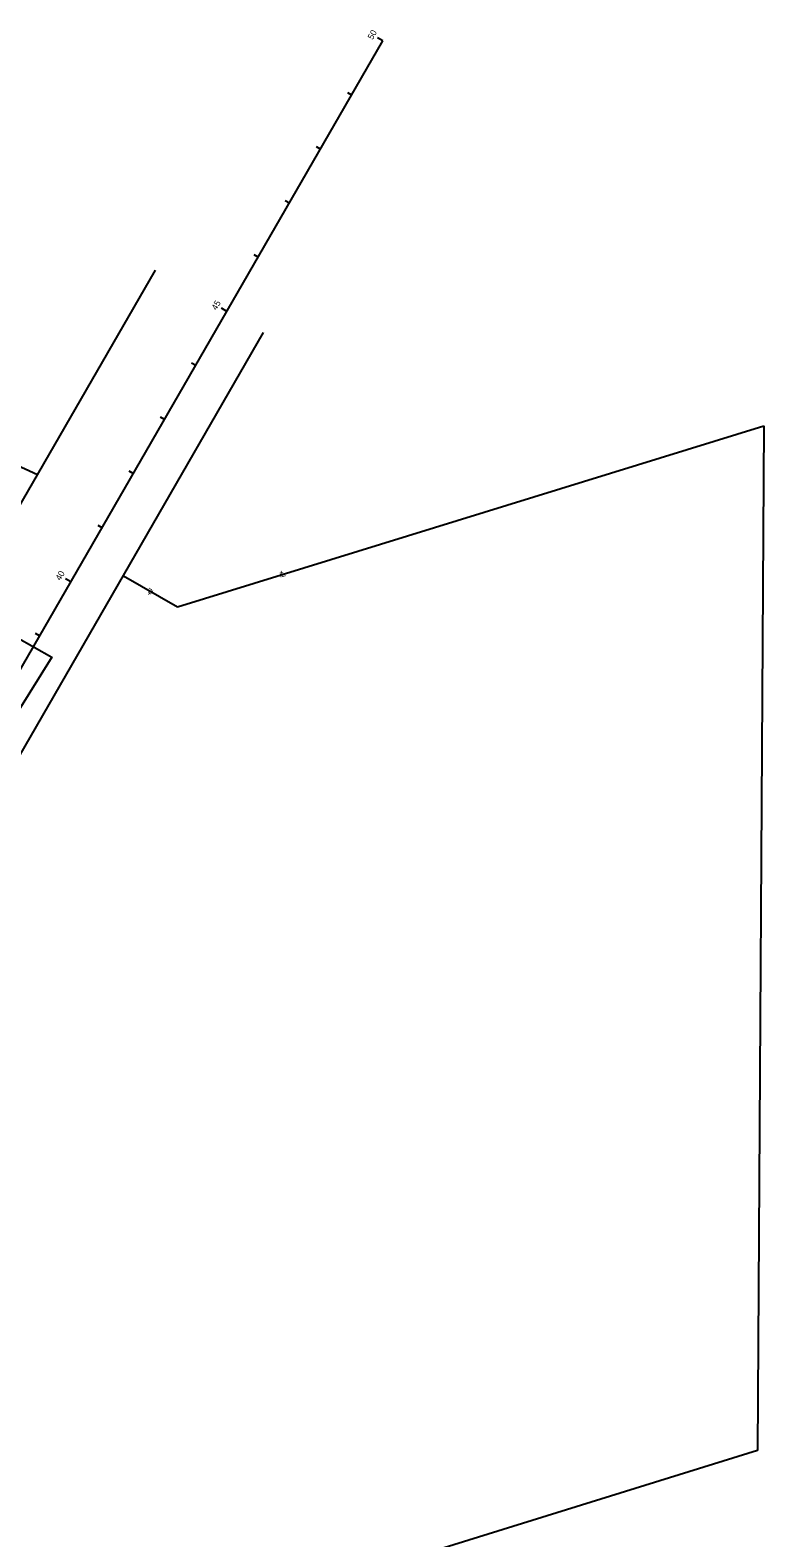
# Model space of a CAD drawing. Extents: x 2003883 to 2008298, y 399149 to 424047.
# Drawn here: x 2007122 to 2008298, y 401725 to 404139 of the extents above; entities that cross this region are included whole.
import ezdxf

# ---------------------------------------------------------------- set-up
doc = ezdxf.new("R2010")
doc.units = 0
for name, color, linetype in [('BaselineSurvey', 7, 'Continuous'), ('BaselineTextWt2', 7, 'Continuous'), ('ConstLimits', 7, 'Continuous'), ('PropertyLine_ep', 7, 'Continuous'), ('PropertyLineSymbol_ep', 7, 'Continuous'), ('RWLine_ep', 7, 'Continuous')]:
    doc.layers.add(name, color=color, linetype=linetype)

msp = doc.modelspace()

# ---------------------------------------------------------------- linework, layer by layer
at = {"layer": 'BaselineSurvey'}
for p, q in [((2006836.2, 402647.3), (2007687.7, 404121.7)), ((2007687.7, 404121.7), (2007679, 404126.7)), ((2007637.7, 404035.1), (2007631.2, 404038.8)), ((2007587.7, 403948.5), (2007581.2, 403952.3)), ((2007537.7, 403861.9), (2007531.2, 403865.7)), ((2007487.6, 403775.3), (2007481.1, 403779.1)), ((2007437.6, 403688.7), (2007429, 403693.7)), ((2007387.6, 403602.1), (2007381.1, 403605.9)), ((2007337.6, 403515.5), (2007331.1, 403519.3)), ((2007287.6, 403428.9), (2007281.1, 403432.7)), ((2007237.6, 403342.3), (2007231.1, 403346.1)), ((2007187.6, 403255.7), (2007178.9, 403260.7)), ((2007137.5, 403169.1), (2007131, 403172.9))]:
    msp.add_line(p, q, dxfattribs=at)
at = {"layer": 'ConstLimits'}
msp.add_lwpolyline([(2006905.3, 403016.3), (2006940.9, 403040.2), (2006950.3, 403046.3), (2006996.5, 403077.4), (2006996.5, 403077.4), (2007023.3, 403080.9), (2007045.2, 403084.4), (2007045.2, 403084.4), (2007053.2, 403085.3), (2007100.6, 403167.3), (2007157, 403135.1), (2007104, 403050)], dxfattribs=at)
at = {"layer": 'PropertyLine_ep'}
for p, q in [((2006528, 403705), (2007134.2, 403427.3)), ((2007358.3, 403215.5), (2008297.9, 403505.4)), ((2008297.9, 403505.4), (2008287.9, 401864.7)), ((2007271.7, 403265.5), (2007358.3, 403215.5)), ((2008287.9, 401864.7), (2006772.4, 401395.2))]:
    msp.add_line(p, q, dxfattribs=at)
at = {"layer": 'RWLine_ep'}
for p, q in [((2006760.6, 402780.4), (2007323.3, 403754.7)), ((2006296.2, 401576.4), (2007496.5, 403654.7))]:
    msp.add_line(p, q, dxfattribs=at)

# ---------------------------------------------------------------- texts
at = {"layer": 'BaselineTextWt2'}
for s, p in [('50', (2007671, 404122.8)), ('45', (2007420.9, 403689.7)), ('40', (2007170.9, 403256.8))]:
    msp.add_text(s, height=10, rotation=59.9911, dxfattribs=at).set_placement(p)
at = {"layer": 'PropertyLineSymbol_ep'}
for s, height, rotation, p in [('P', 7.5, 14.1969, (2007523.2, 403262.7)), ('L', 10, 14.1969, (2007525.2, 403263.2)), ('L', 10, 147.2291, (2007318.7, 403242.5)), ('P', 7.5, 147.2291, (2007320.4, 403241.3))]:
    msp.add_text(s, height=height, rotation=rotation, dxfattribs=at).set_placement(p)

doc.saveas('drawing.dxf')
